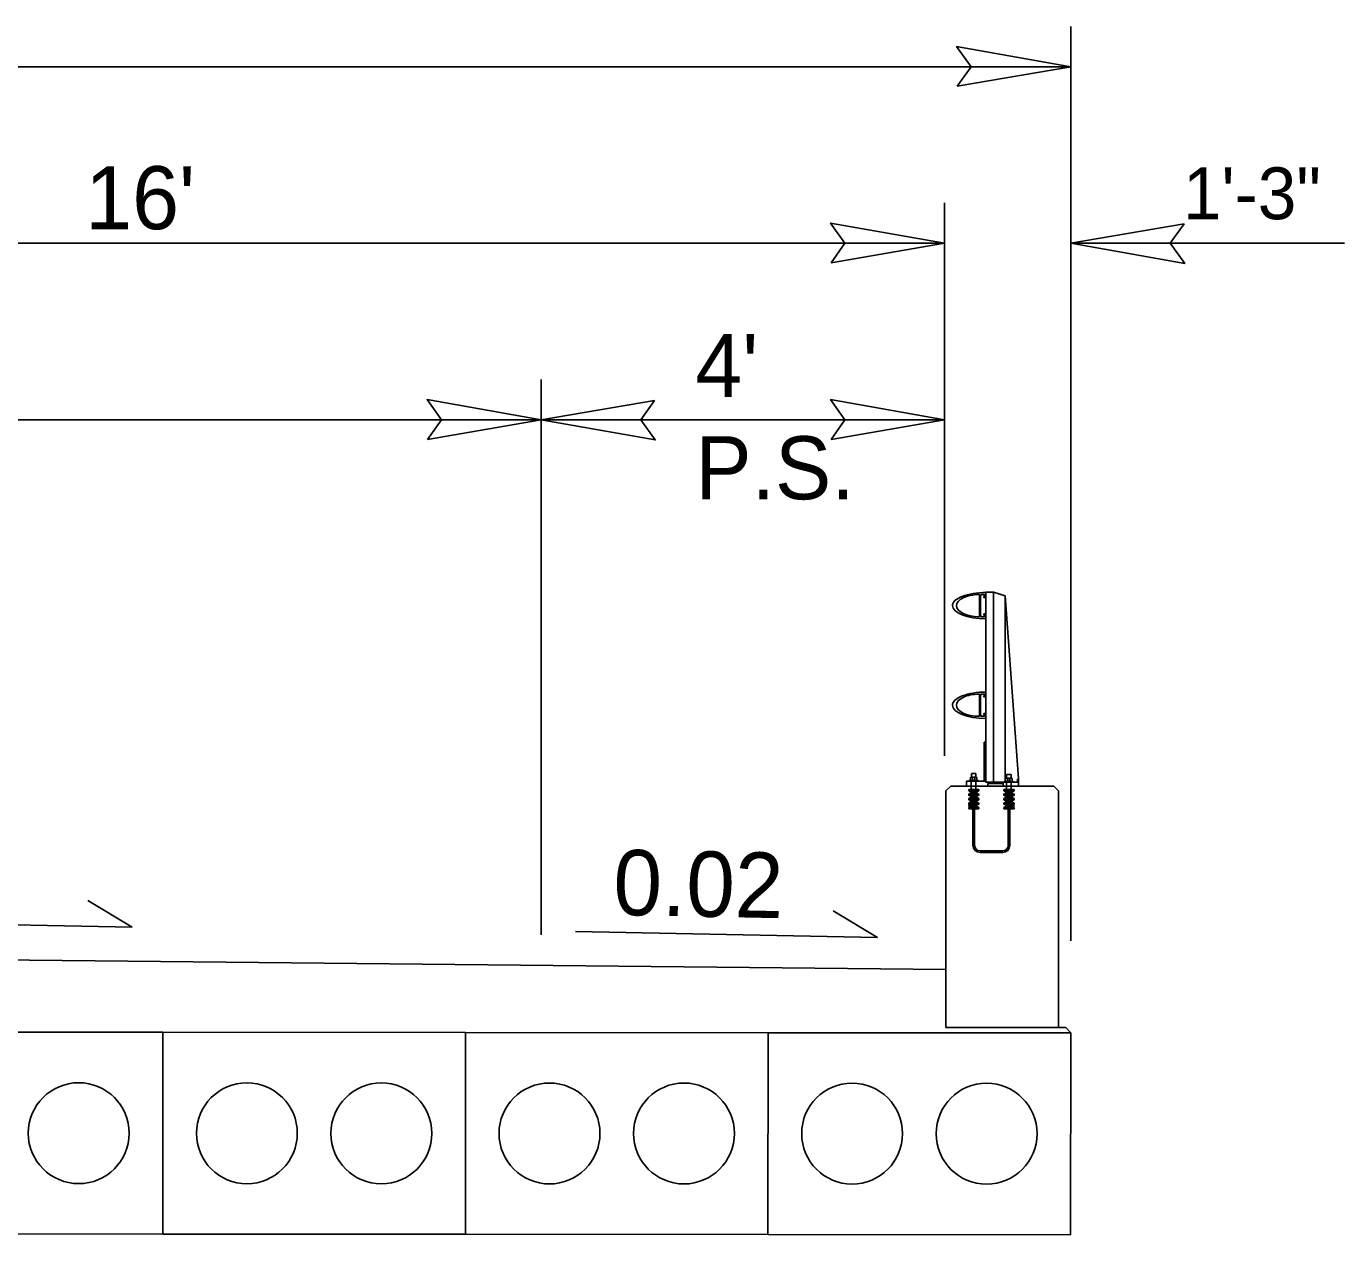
# Model space of a CAD drawing. Extents: x 1733676 to 1734289, y 540979 to 541226.
# Drawn here: x 1734040.68 to 1734053.75, y 541157.13 to 541169.11 of the extents above; entities that cross this region are included whole.
import ezdxf

# ---------------------------------------------------------------- set-up
doc = ezdxf.new("R2010")
doc.units = 0
for name, color, linetype in [('Prop Dimension', 7, 'Continuous'), ('Prop Terminator CELL', 7, 'Continuous'), ('Typical Bridge Rail Two Bar CELL', 7, 'Continuous'), ('Typical Pavement Slope CELL', 7, 'Continuous'), ('Typical Pavement Slope Information CELL', 7, 'Continuous'), ('Typical Slope Point Local CELL', 7, 'Continuous')]:
    doc.layers.add(name, color=color, linetype=linetype)

msp = doc.modelspace()

# ---------------------------------------------------------------- linework, layer by layer
at = {"layer": 'Prop Dimension'}
for p, q in [((1734051.037, 541160.046), (1734051.037, 541169.109)), ((1734051.037, 541168.709), (1734006.037, 541168.709)), ((1734049.787, 541161.879), (1734049.787, 541167.359)), ((1734049.787, 541166.959), (1734033.787, 541166.959)), ((1734051.037, 541166.959), (1734053.752, 541166.959)), ((1734045.787, 541160.103), (1734045.787, 541165.609)), ((1734045.787, 541165.209), (1734033.787, 541165.209)), ((1734049.787, 541165.209), (1734045.787, 541165.209)), ((1734042.037, 541159.138), (1734039.037, 541159.14)), ((1734042.036, 541157.138), (1734042.037, 541159.138)), ((1734042.036, 541157.138), (1734042.037, 541159.138)), ((1734045.037, 541159.136), (1734042.037, 541159.138)), ((1734045.036, 541157.136), (1734045.037, 541159.136)), ((1734045.036, 541157.136), (1734045.037, 541159.136)), ((1734048.037, 541159.134), (1734045.037, 541159.136)), ((1734048.036, 541157.134), (1734048.037, 541159.134)), ((1734048.036, 541157.134), (1734048.037, 541159.134)), ((1734051.037, 541159.132), (1734048.037, 541159.134)), ((1734051.036, 541157.132), (1734051.037, 541159.132)), ((1734042.036, 541157.138), (1734039.036, 541157.14)), ((1734045.036, 541157.136), (1734042.036, 541157.138)), ((1734048.036, 541157.134), (1734045.036, 541157.136)), ((1734051.036, 541157.132), (1734048.036, 541157.134))]:
    msp.add_line(p, q, dxfattribs=at)
for centre in [(1734041.203, 541158.138), (1734042.87, 541158.137), (1734044.203, 541158.136), (1734045.87, 541158.135), (1734047.203, 541158.135), (1734048.87, 541158.134), (1734050.203, 541158.133)]:
    msp.add_circle(centre, 0.5, dxfattribs=at)
at = {"layer": 'Prop Terminator CELL'}
for points in [[(1734049.912, 541168.515), (1734051.037, 541168.709), (1734049.906, 541168.909), (1734050.049, 541168.709)], [(1734048.662, 541166.765), (1734049.787, 541166.959), (1734048.656, 541167.159), (1734048.799, 541166.959)], [(1734052.162, 541167.152), (1734051.037, 541166.959), (1734052.168, 541166.759), (1734052.024, 541166.959)], [(1734044.662, 541165.015), (1734045.787, 541165.209), (1734044.656, 541165.409), (1734044.799, 541165.209)], [(1734046.912, 541165.402), (1734045.787, 541165.209), (1734046.918, 541165.009), (1734046.774, 541165.209)], [(1734048.662, 541165.015), (1734049.787, 541165.209), (1734048.656, 541165.409), (1734048.799, 541165.209)]]:
    msp.add_lwpolyline(points, close=True, dxfattribs=at)
at = {"layer": 'Typical Bridge Rail Two Bar CELL'}
for p, q in [((1734050.134, 541163.469), (1734050.134, 541163.367)), ((1734050.197, 541163.501), (1734050.273, 541163.501)), ((1734050.197, 541161.617), (1734050.197, 541163.501)), ((1734050.387, 541163.463), (1734050.273, 541163.501)), ((1734050.273, 541161.617), (1734050.273, 541163.501)), ((1734050.387, 541161.617), (1734050.387, 541163.463)), ((1734050.387, 541163.463), (1734050.518, 541161.655)), ((1734050.134, 541163.265), (1734050.134, 541163.367)), ((1734050.387, 541162.599), (1734050.391, 541162.599)), ((1734050.134, 541162.482), (1734050.134, 541162.38)), ((1734050.134, 541162.278), (1734050.134, 541162.38)), ((1734050.051, 541161.543), (1734050.051, 541161.627)), ((1734050.053, 541161.668), (1734050.053, 541161.703)), ((1734050.053, 541161.703), (1734050.096, 541161.703)), ((1734050.096, 541161.703), (1734050.096, 541161.668)), ((1734050.098, 541161.543), (1734050.098, 541161.627)), ((1734050.402, 541161.658), (1734050.402, 541161.693)), ((1734050.402, 541161.693), (1734050.445, 541161.693)), ((1734050.402, 541161.534), (1734050.402, 541161.617)), ((1734050.445, 541161.693), (1734050.445, 541161.658)), ((1734050.446, 541161.534), (1734050.446, 541161.617)), ((1734050.515, 541161.676), (1734050.515, 541161.709)), ((1734050.518, 541161.617), (1734050.518, 541161.655)), ((1734049.848, 541161.579), (1734049.799, 541161.531)), ((1734049.799, 541161.531), (1734049.799, 541159.186)), ((1734049.848, 541161.579), (1734050.868, 541161.579)), ((1734050.026, 541161.543), (1734050.126, 541161.543)), ((1734050.026, 541161.532), (1734050.126, 541161.532)), ((1734050.026, 541161.499), (1734050.068, 541161.499)), ((1734050.026, 541161.488), (1734050.068, 541161.488)), ((1734050.048, 541161.521), (1734050.068, 541161.521)), ((1734050.048, 541161.51), (1734050.068, 541161.51)), ((1734050.048, 541161.476), (1734050.068, 541161.476)), ((1734050.068, 541161.521), (1734050.084, 541161.521)), ((1734050.068, 541161.521), (1734050.068, 541160.99)), ((1734050.084, 541161.521), (1734050.104, 541161.521)), ((1734050.084, 541161.521), (1734050.084, 541160.99)), ((1734050.084, 541161.51), (1734050.104, 541161.51)), ((1734050.084, 541161.499), (1734050.126, 541161.499)), ((1734050.084, 541161.488), (1734050.126, 541161.488)), ((1734050.084, 541161.476), (1734050.104, 541161.476)), ((1734050.374, 541161.543), (1734050.475, 541161.543)), ((1734050.374, 541161.532), (1734050.475, 541161.532)), ((1734050.374, 541161.499), (1734050.416, 541161.499)), ((1734050.374, 541161.488), (1734050.416, 541161.488)), ((1734050.397, 541161.521), (1734050.416, 541161.521)), ((1734050.397, 541161.51), (1734050.416, 541161.51)), ((1734050.397, 541161.476), (1734050.416, 541161.476)), ((1734050.416, 541161.521), (1734050.433, 541161.521)), ((1734050.416, 541161.521), (1734050.416, 541160.99)), ((1734050.433, 541161.521), (1734050.453, 541161.521)), ((1734050.433, 541161.521), (1734050.433, 541160.99)), ((1734050.433, 541161.51), (1734050.453, 541161.51)), ((1734050.433, 541161.499), (1734050.475, 541161.499)), ((1734050.433, 541161.488), (1734050.475, 541161.488)), ((1734050.433, 541161.476), (1734050.453, 541161.476)), ((1734050.917, 541161.531), (1734050.868, 541161.579)), ((1734050.917, 541161.531), (1734050.917, 541159.186)), ((1734050.026, 541161.454), (1734050.068, 541161.454)), ((1734050.026, 541161.443), (1734050.068, 541161.443)), ((1734050.026, 541161.41), (1734050.068, 541161.41)), ((1734050.026, 541161.399), (1734050.068, 541161.399)), ((1734050.026, 541161.365), (1734050.068, 541161.365)), ((1734050.026, 541161.354), (1734050.068, 541161.354)), ((1734050.048, 541161.465), (1734050.068, 541161.465)), ((1734050.048, 541161.432), (1734050.068, 541161.432)), ((1734050.048, 541161.421), (1734050.068, 541161.421)), ((1734050.048, 541161.388), (1734050.068, 541161.388)), ((1734050.048, 541161.377), (1734050.068, 541161.377)), ((1734050.084, 541161.465), (1734050.104, 541161.465)), ((1734050.084, 541161.454), (1734050.126, 541161.454)), ((1734050.084, 541161.443), (1734050.126, 541161.443)), ((1734050.084, 541161.432), (1734050.104, 541161.432)), ((1734050.084, 541161.421), (1734050.104, 541161.421)), ((1734050.084, 541161.41), (1734050.126, 541161.41)), ((1734050.084, 541161.399), (1734050.126, 541161.399)), ((1734050.084, 541161.388), (1734050.104, 541161.388)), ((1734050.084, 541161.377), (1734050.104, 541161.377)), ((1734050.084, 541161.365), (1734050.126, 541161.365)), ((1734050.084, 541161.354), (1734050.126, 541161.354)), ((1734050.374, 541161.454), (1734050.416, 541161.454)), ((1734050.374, 541161.443), (1734050.416, 541161.443)), ((1734050.374, 541161.41), (1734050.416, 541161.41)), ((1734050.374, 541161.399), (1734050.416, 541161.399)), ((1734050.374, 541161.365), (1734050.416, 541161.365)), ((1734050.374, 541161.354), (1734050.416, 541161.354)), ((1734050.397, 541161.465), (1734050.416, 541161.465)), ((1734050.397, 541161.432), (1734050.416, 541161.432)), ((1734050.397, 541161.421), (1734050.416, 541161.421)), ((1734050.397, 541161.388), (1734050.416, 541161.388)), ((1734050.397, 541161.377), (1734050.416, 541161.377)), ((1734050.433, 541161.465), (1734050.453, 541161.465)), ((1734050.433, 541161.454), (1734050.475, 541161.454)), ((1734050.433, 541161.443), (1734050.475, 541161.443)), ((1734050.433, 541161.432), (1734050.453, 541161.432)), ((1734050.433, 541161.421), (1734050.453, 541161.421)), ((1734050.433, 541161.41), (1734050.475, 541161.41)), ((1734050.433, 541161.399), (1734050.475, 541161.399)), ((1734050.433, 541161.388), (1734050.453, 541161.388)), ((1734050.433, 541161.377), (1734050.453, 541161.377)), ((1734050.433, 541161.365), (1734050.475, 541161.365)), ((1734050.433, 541161.354), (1734050.475, 541161.354)), ((1734050.138, 541160.937), (1734050.363, 541160.937)), ((1734050.138, 541160.92), (1734050.363, 541160.92)), ((1734049.799, 541159.186), (1734050.907, 541159.186)), ((1734050.907, 541159.186), (1734050.988, 541159.186)), ((1734051.037, 541159.132), (1734050.988, 541159.186))]:
    msp.add_line(p, q, dxfattribs=at)
for points in [[(1734050.197, 541163.237), (1734050.197, 541163.285), (1734050.177, 541163.285), (1734050.177, 541163.277), (1734050.179, 541163.277), (1734050.179, 541163.257), (1734050.147, 541163.257), (1734050.143, 541163.288), (1734050.143, 541163.367), (1734050.143, 541163.446), (1734050.147, 541163.477), (1734050.179, 541163.477), (1734050.179, 541163.457), (1734050.177, 541163.457), (1734050.177, 541163.449), (1734050.197, 541163.449), (1734050.197, 541163.498)], [(1734050.197, 541162.249), (1734050.197, 541162.298), (1734050.177, 541162.298), (1734050.177, 541162.29), (1734050.179, 541162.29), (1734050.179, 541162.27), (1734050.147, 541162.27), (1734050.143, 541162.301), (1734050.143, 541162.38), (1734050.143, 541162.459), (1734050.147, 541162.49), (1734050.179, 541162.49), (1734050.179, 541162.47), (1734050.177, 541162.47), (1734050.177, 541162.462), (1734050.197, 541162.462), (1734050.197, 541162.51)], [(1734050.004, 541161.579), (1734050.004, 541161.627), (1734050.179, 541161.627), (1734050.179, 541162.013), (1734050.197, 541162.013), (1734050.197, 541161.617), (1734050.509, 541161.617), (1734050.509, 541161.645), (1734050.518, 541161.645), (1734050.518, 541161.579), (1734050.368, 541161.579), (1734050.368, 541161.605), (1734050.216, 541161.605), (1734050.216, 541161.579), (1734050.004, 541161.579)], [(1734050.031, 541161.626), (1734050.031, 541161.635), (1734050.074, 541161.635), (1734050.117, 541161.635), (1734050.117, 541161.626)], [(1734050.043, 541161.634), (1734050.043, 541161.662), (1734050.048, 541161.667), (1734050.101, 541161.667), (1734050.106, 541161.662), (1734050.106, 541161.634), (1734050.043, 541161.634), (1734050.064, 541161.634), (1734050.064, 541161.662), (1734050.059, 541161.667), (1734050.064, 541161.662), (1734050.069, 541161.667), (1734050.08, 541161.667), (1734050.085, 541161.662), (1734050.085, 541161.634), (1734050.085, 541161.662), (1734050.09, 541161.667)], [(1734050.381, 541161.617), (1734050.381, 541161.625), (1734050.424, 541161.625), (1734050.466, 541161.625), (1734050.466, 541161.617)], [(1734050.392, 541161.625), (1734050.392, 541161.652), (1734050.397, 541161.658), (1734050.45, 541161.658), (1734050.455, 541161.652), (1734050.455, 541161.625), (1734050.392, 541161.625), (1734050.413, 541161.625), (1734050.413, 541161.652), (1734050.408, 541161.658), (1734050.413, 541161.652), (1734050.418, 541161.658), (1734050.429, 541161.658), (1734050.434, 541161.652), (1734050.434, 541161.625), (1734050.434, 541161.652), (1734050.44, 541161.658)], [(1734050.026, 541161.543), (1734050.026, 541161.532), (1734050.048, 541161.521), (1734050.048, 541161.51), (1734050.026, 541161.499), (1734050.026, 541161.488), (1734050.048, 541161.476), (1734050.048, 541161.465), (1734050.026, 541161.454), (1734050.026, 541161.443), (1734050.048, 541161.432), (1734050.048, 541161.421), (1734050.026, 541161.41), (1734050.026, 541161.399), (1734050.048, 541161.388), (1734050.048, 541161.377), (1734050.026, 541161.365), (1734050.026, 541161.354)], [(1734050.126, 541161.543), (1734050.126, 541161.532), (1734050.104, 541161.521), (1734050.104, 541161.51), (1734050.126, 541161.499), (1734050.126, 541161.488), (1734050.104, 541161.476), (1734050.104, 541161.465), (1734050.126, 541161.454), (1734050.126, 541161.443), (1734050.104, 541161.432), (1734050.104, 541161.421), (1734050.126, 541161.41), (1734050.126, 541161.399), (1734050.104, 541161.388), (1734050.104, 541161.377), (1734050.126, 541161.365), (1734050.126, 541161.354)], [(1734050.374, 541161.543), (1734050.374, 541161.532), (1734050.396, 541161.521), (1734050.396, 541161.51), (1734050.374, 541161.499), (1734050.374, 541161.488), (1734050.396, 541161.476), (1734050.396, 541161.465), (1734050.374, 541161.454), (1734050.374, 541161.443), (1734050.396, 541161.432), (1734050.396, 541161.421), (1734050.374, 541161.41), (1734050.374, 541161.399), (1734050.396, 541161.388), (1734050.396, 541161.377), (1734050.374, 541161.365), (1734050.374, 541161.354)], [(1734050.475, 541161.543), (1734050.475, 541161.532), (1734050.453, 541161.521), (1734050.453, 541161.51), (1734050.475, 541161.499), (1734050.475, 541161.488), (1734050.453, 541161.476), (1734050.453, 541161.465), (1734050.475, 541161.454), (1734050.475, 541161.443), (1734050.453, 541161.432), (1734050.453, 541161.421), (1734050.475, 541161.41), (1734050.475, 541161.399), (1734050.453, 541161.388), (1734050.453, 541161.377), (1734050.475, 541161.365), (1734050.475, 541161.354)]]:
    msp.add_lwpolyline(points, dxfattribs=at)
for centre in [(1734050.035, 541161.382), (1734050.466, 541161.382)]:
    msp.add_circle(centre, 0.00834, dxfattribs=at)
for centre, radius, start, end in [((1734050.127, 541163.469), 0.00783, 0, 90), ((1734050.127, 541163.265), 0.00783, 270, 0), ((1734050.127, 541162.482), 0.00783, 0, 90), ((1734050.127, 541162.278), 0.00783, 270, 0), ((1734050.138, 541160.99), 0.07, 180, 270), ((1734050.138, 541160.99), 0.0534, 180, 270), ((1734050.363, 541160.99), 0.0534, 270, 0), ((1734050.363, 541160.99), 0.07, 270, 0)]:
    msp.add_arc(centre, radius, start, end, dxfattribs=at)
for centre, major_axis, ratio, start_param, end_param in [((1734050.198, 541163.367), (-0.334, 0), 0.39036, 4.712404, 6.283584), ((1734050.127, 541163.367), (-0.222, 0), 0.495501, 4.712489, 6.283652), ((1734050.198, 541163.367), (-0.334, 0), 0.39036, 0.000398, 1.570782), ((1734050.127, 541163.367), (-0.222, 0), 0.495501, 0.000467, 1.570696), ((1734050.198, 541162.38), (-0.334, 0), 0.39036, 4.712404, 6.283584), ((1734050.127, 541162.38), (-0.222, 0), 0.495501, 4.712489, 6.283652), ((1734050.198, 541162.38), (-0.334, 0), 0.39036, 0.000398, 1.570782), ((1734050.127, 541162.38), (-0.222, 0), 0.495501, 0.000467, 1.570696)]:
    msp.add_ellipse(centre, major_axis=major_axis, ratio=ratio, start_param=start_param, end_param=end_param, dxfattribs=at)
at = {"layer": 'Typical Pavement Slope CELL'}
msp.add_line((1734049.799, 541159.762), (1734033.787, 541159.925), dxfattribs=at)
at = {"layer": 'Typical Pavement Slope Information CELL'}
for p, q in [((1734041.733, 541160.181), (1734041.295, 541160.446)), ((1734049.12, 541160.078), (1734048.683, 541160.343)), ((1734041.733, 541160.181), (1734038.741, 541160.241)), ((1734049.12, 541160.078), (1734046.129, 541160.138))]:
    msp.add_line(p, q, dxfattribs=at)

# ---------------------------------------------------------------- texts
msp.add_text('0.02', height=0.6476, rotation=358.8543, dxfattribs=at).set_placement((1734046.498, 541160.302))
at = {"layer": 'Typical Slope Point Local CELL'}
for s, height, p in [("16'", 0.6249, (1734041.268, 541167.098)), ('1\'-3"', 0.5141, (1734052.149, 541167.197)), ("4'", 0.6249, (1734047.316, 541165.436)), ('P.S.', 0.6249, (1734047.316, 541164.421))]:
    msp.add_text(s, height=height, rotation=360, dxfattribs=at).set_placement(p)

doc.saveas('drawing.dxf')
